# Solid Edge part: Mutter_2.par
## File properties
Sűrűség: 0,000 kg/m^3
Pontosság: 0,990
Author: ahadarics
Last saved by: ahadarics
Revision: 76
Username: ahadarics
Dokumentum tartalom típus: 0
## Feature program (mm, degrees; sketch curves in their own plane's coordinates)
base feature "unnamed BaseFeature 1"
thread "unnamed Thread 1"
chamfer "unnamed Chamfer 1"
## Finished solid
Body 1: solid body, 23 faces, 46 edges, 24 vertices.
  Faces by surface: cone 14, plane 8, cylinder 1
  Edges by curve: spline 24, circle 16, line 6
Bounding box of the edges (mm): 6.000 x 19.630 x 17.000, from (0, -9.815, -8.5) to (6, 9.815, 8.5).
Cylindrical faces by radius (mm): R4.3235 x1
Conical faces (half-angle, radius in mm at the cone's reference point): 45 deg R4.3235 x1, 45 deg R4.7235 x1, 60 deg R9.1575 x12
Planar faces by outward normal: +x 1, +z 1, -x 1, -z 1, oblique 4
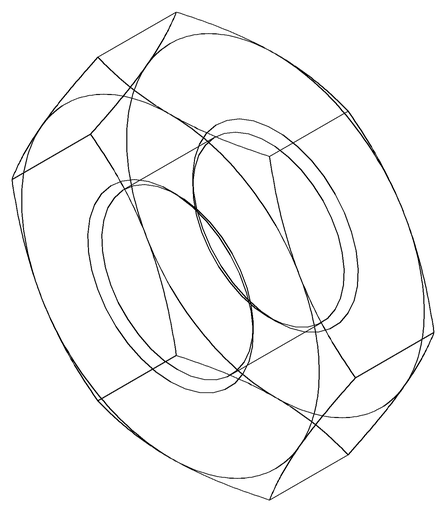
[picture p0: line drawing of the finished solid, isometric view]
